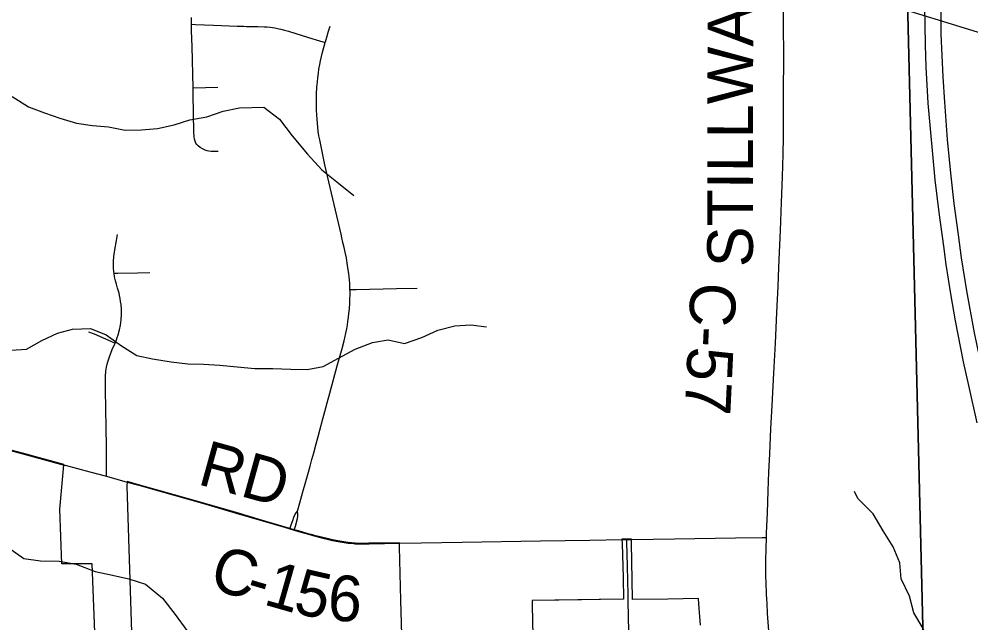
# Model space of a CAD drawing. Extents: x -6.4 to 34, y -4.2 to 22.
# Drawn here: x 5.93 to 7.115, y 16.08 to 16.831 of the extents above; entities that cross this region are included whole.
import ezdxf

# ---------------------------------------------------------------- set-up
doc = ezdxf.new("R2010")
doc.units = 0
for name, color, linetype in [('GM_X_City_Street', 7, 'Continuous'), ('GM_X_Corporation', 7, 'Continuous'), ('GM_X_County_Road', 7, 'Continuous'), ('GM_X_County_Road_Text', 7, 'Continuous'), ('GM_X_Minor_River', 7, 'Continuous'), ('GM_X_State_Route', 7, 'Continuous'), ('GM_X_Township_Road', 7, 'Continuous'), ('SH_Text', 7, 'Continuous')]:
    doc.layers.add(name, color=color, linetype=linetype)

msp = doc.modelspace()

# ---------------------------------------------------------------- linework, layer by layer
at = {"layer": 'GM_X_City_Street'}
msp.add_lwpolyline([(6.6887, 16.07), (6.6883, 16.0873), (6.6878, 16.1073), (6.6877, 16.1153), (6.6869, 16.15), (6.6863, 16.1805), (6.6862, 16.1837)], dxfattribs=at)
at = {"layer": 'GM_X_Corporation'}
for points in [[(7.0203, 17.4801), (7.0556, 16.0421), (7.0636, 15.9014), (7.2702, 15.904), (7.2926, 15.9044), (8.6815, 15.9311), (8.9, 15.9356), (8.9, 20.7065)], [(5.7185, 15.8776), (6.5599, 15.8933), (6.7596, 15.897), (6.8667, 15.898), (7.0636, 15.9014), (7.0556, 16.0421), (7.0203, 17.4801)], [(6.0241, 16.0683), (6.0209, 16.1536), (5.9979, 16.1536), (5.983, 16.1536), (5.9805, 16.2214), (5.9852, 16.2717), (5.9857, 16.277), (5.9342, 16.2911), (5.8874, 16.3034)], [(6.41, 15.9369), (6.405, 16.1081), (6.4035, 16.1745), (6.4035, 16.1797), (6.3653, 16.179), (6.3609, 16.1789), (6.356, 16.1788), (6.3519, 16.1789), (6.348, 16.1791), (6.3436, 16.1795), (6.3394, 16.1799), (6.3341, 16.1807), (6.329, 16.1815), (6.3244, 16.1824), (6.3199, 16.1833), (6.3132, 16.1849), (6.3078, 16.1861), (6.303, 16.1874), (6.2987, 16.1885), (6.2952, 16.1894), (6.2898, 16.1908), (6.2775, 16.1944), (6.2722, 16.1959), (6.2668, 16.1975), (6.26, 16.1995), (6.2314, 16.208), (6.1999, 16.2173), (6.1581, 16.2293), (6.1037, 16.2448), (6.0786, 16.2518), (6.0643, 16.2559), (6.0641, 16.2503), (6.0698, 16.0683)], [(6.7779, 16.077), (6.7758, 16.1035), (6.7753, 16.1103), (6.7372, 16.1096), (6.6934, 16.1089), (6.6929, 16.1335), (6.692, 16.179), (6.6919, 16.1843), (6.686, 16.1842), (6.6802, 16.1841), (6.6806, 16.1788), (6.6815, 16.1361), (6.682, 16.1095), (6.6536, 16.1091), (6.6517, 16.1091), (6.6299, 16.1088), (6.6252, 16.1087), (6.6015, 16.1083), (6.5967, 16.1083), (6.5683, 16.1078), (6.5684, 16.1021), (6.5692, 16.0635)]]:
    msp.add_lwpolyline(points, dxfattribs=at)
at = {"layer": 'GM_X_County_Road'}
for points in [[(6.8601, 16.1863), (6.8602, 16.1918), (6.8612, 16.2171), (6.8622, 16.2442), (6.8631, 16.2674), (6.8641, 16.2903), (6.8656, 16.3213), (6.867, 16.3503), (6.869, 16.3908), (6.8711, 16.4282), (6.873, 16.4662), (6.8746, 16.4987), (6.8756, 16.5224), (6.8763, 16.5414), (6.8773, 16.5684), (6.8787, 16.6032), (6.8799, 16.635), (6.8807, 16.6631), (6.8812, 16.6844), (6.8813, 16.706), (6.8814, 16.7372), (6.8815, 16.7863), (6.8811, 16.8228), (6.8808, 16.8652)], [(5.7737, 16.3333), (5.7748, 16.333), (5.8511, 16.3126), (5.8876, 16.3028), (5.9344, 16.2905), (5.9862, 16.2763)], [(5.9862, 16.2763), (5.9871, 16.2761), (6.0178, 16.268), (6.0386, 16.2624), (6.0645, 16.2553)], [(6.0645, 16.2553), (6.0788, 16.2513), (6.1039, 16.2442), (6.1583, 16.2288), (6.2001, 16.2167), (6.2316, 16.2075), (6.2602, 16.1989), (6.267, 16.1969), (6.2724, 16.1954), (6.2777, 16.1939), (6.29, 16.1903), (6.2954, 16.1889), (6.2989, 16.188), (6.3032, 16.1868), (6.308, 16.1856), (6.3134, 16.1843), (6.3201, 16.1827), (6.3246, 16.1818), (6.3292, 16.1809), (6.3343, 16.1801), (6.3396, 16.1794), (6.3438, 16.179), (6.3482, 16.1785), (6.3521, 16.1784), (6.3562, 16.1782), (6.3611, 16.1783), (6.3655, 16.1784), (6.4037, 16.1791)], [(6.4037, 16.1791), (6.4301, 16.1795), (6.4813, 16.1803), (6.5789, 16.182), (6.6404, 16.183), (6.6804, 16.1836)], [(6.6804, 16.1836), (6.6862, 16.1837), (6.6926, 16.1837)], [(6.6926, 16.1837), (6.7456, 16.1845), (6.8213, 16.1858), (6.8547, 16.1862), (6.8601, 16.1863)], [(6.8691, 15.9507), (6.8687, 15.9618), (6.8684, 15.9792), (6.8667, 16.0136), (6.8642, 16.0529), (6.8634, 16.0641), (6.8626, 16.0757), (6.8615, 16.0918), (6.8607, 16.1041), (6.8604, 16.1098), (6.8602, 16.1153), (6.8599, 16.121), (6.8597, 16.1252), (6.8595, 16.1312), (6.8593, 16.1369), (6.8593, 16.1416), (6.8592, 16.1465), (6.8593, 16.1529), (6.8594, 16.1582), (6.8601, 16.1863)]]:
    msp.add_lwpolyline(points, dxfattribs=at)
at = {"layer": 'GM_X_Minor_River'}
for points in [[(5.9211, 16.7349), (5.9415, 16.7223), (5.9615, 16.7146), (5.9808, 16.708), (6.0012, 16.7019), (6.0212, 16.6991), (6.0413, 16.6971), (6.0621, 16.6932), (6.0822, 16.6935), (6.1022, 16.6953), (6.1227, 16.6998), (6.1424, 16.7061), (6.1637, 16.7098), (6.1838, 16.7166), (6.2042, 16.721), (6.2345, 16.7217), (6.2541, 16.7067), (6.2699, 16.6862), (6.2887, 16.6633), (6.3067, 16.6438), (6.3275, 16.627), (6.3467, 16.6117)], [(5.9199, 16.4193), (5.9392, 16.4207), (5.9582, 16.4313), (5.9776, 16.4407), (5.9965, 16.4455), (6.0189, 16.4462), (6.0381, 16.4385), (6.0574, 16.4247), (6.0766, 16.4128), (6.0959, 16.4086), (6.1193, 16.4047), (6.1398, 16.4023), (6.1594, 16.4018), (6.1799, 16.4006), (6.2014, 16.3986), (6.2234, 16.3966), (6.2457, 16.3965), (6.2681, 16.3956), (6.2885, 16.3955), (6.3082, 16.3992), (6.3276, 16.4094), (6.3481, 16.4207), (6.3697, 16.4289), (6.3891, 16.4323), (6.4095, 16.4276), (6.4311, 16.4351), (6.4509, 16.4441), (6.4721, 16.4497), (6.4922, 16.4508), (6.5115, 16.4484)], [(7.1193, 15.8737), (7.0998, 15.8912), (7.0832, 15.911), (7.0765, 15.9308), (7.0744, 15.951), (7.0756, 15.9711), (7.0697, 15.9912), (7.0679, 16.0114), (7.062, 16.0311), (7.0614, 16.0528), (7.0551, 16.073), (7.0435, 16.0924), (7.0379, 16.1133), (7.0278, 16.135), (7.0261, 16.1547), (7.0175, 16.1745), (7.0051, 16.1947), (6.9927, 16.2157), (6.9739, 16.2347), (6.9694, 16.2435)], [(5.9161, 16.1743), (5.9357, 16.1602), (5.9565, 16.1574), (5.9796, 16.1566), (6.0011, 16.153), (6.0245, 16.1438), (6.0461, 16.1395), (6.0665, 16.1349), (6.0873, 16.1283), (6.1084, 16.1108), (6.1242, 16.0906), (6.1388, 16.0707)]]:
    msp.add_lwpolyline(points, dxfattribs=at)
at = {"layer": 'GM_X_State_Route'}
for points in [[(7.2156, 16.091), (7.2133, 16.0975), (7.206, 16.117), (7.188, 16.1712), (7.168, 16.2365), (7.1566, 16.2779), (7.137, 16.356), (7.1276, 16.3999), (7.1189, 16.4411), (7.1092, 16.4931), (7.1027, 16.5343), (7.0988, 16.5627), (7.0937, 16.6018), (7.0894, 16.6395), (7.0855, 16.6813), (7.0818, 16.7279), (7.08, 16.7594), (7.0776, 16.8125), (7.0772, 16.8681)], [(7.1223, 16.3289), (7.1117, 16.3752), (7.1054, 16.4049), (7.0953, 16.4558), (7.0896, 16.4895), (7.0837, 16.5258), (7.0806, 16.5487), (7.0749, 16.5907), (7.0699, 16.6313), (7.0611, 16.7268), (7.0588, 16.7718), (7.058, 16.7993), (7.0571, 16.8478)]]:
    msp.add_lwpolyline(points, dxfattribs=at)
at = {"layer": 'GM_X_Township_Road'}
msp.add_line((6.1464, 16.7456), (6.1771, 16.7465), dxfattribs=at)
for points in [[(6.8601, 16.1863), (6.8602, 16.1918), (6.8612, 16.2171), (6.8622, 16.2442), (6.8631, 16.2674), (6.8641, 16.2903), (6.8656, 16.3213), (6.867, 16.3503), (6.869, 16.3908), (6.8711, 16.4282), (6.873, 16.4662), (6.8746, 16.4987), (6.8756, 16.5224), (6.8763, 16.5414), (6.8773, 16.5684), (6.8787, 16.6032), (6.8799, 16.635), (6.8807, 16.6631), (6.8812, 16.6844), (6.8813, 16.706), (6.8814, 16.7372), (6.8815, 16.7863), (6.8811, 16.8228), (6.8808, 16.8652)], [(6.1776, 16.6664), (6.1715, 16.6665), (6.169, 16.6665), (6.166, 16.6668), (6.1638, 16.6673), (6.1616, 16.6681), (6.158, 16.6699), (6.1551, 16.6717), (6.1528, 16.6735), (6.1512, 16.6752), (6.1499, 16.6771), (6.1489, 16.6793), (6.1481, 16.6821), (6.1476, 16.6851), (6.1473, 16.6906), (6.1466, 16.7378), (6.1464, 16.7456), (6.1451, 16.7974), (6.1444, 16.8168), (6.1443, 16.8248), (6.1443, 16.8334)], [(6.1443, 16.8248), (6.1495, 16.8246), (6.1719, 16.8239), (6.2014, 16.8226), (6.206, 16.8225), (6.2097, 16.8224), (6.2131, 16.8223), (6.2141, 16.8223), (6.22, 16.8221), (6.2271, 16.822), (6.2352, 16.8218), (6.2388, 16.8216), (6.2425, 16.8213), (6.248, 16.8206), (6.2513, 16.8198), (6.2558, 16.8188), (6.2603, 16.8176), (6.2653, 16.8162), (6.2902, 16.8084), (6.3039, 16.8043), (6.311, 16.8022)], [(6.2724, 16.1954), (6.2738, 16.2004), (6.2763, 16.2097), (6.2766, 16.2127), (6.2766, 16.2159), (6.2763, 16.2191), (6.2793, 16.2293), (6.2832, 16.2431), (6.2868, 16.2558), (6.2893, 16.2646), (6.2921, 16.2751), (6.2942, 16.2831), (6.2966, 16.2918), (6.2996, 16.3029), (6.3021, 16.3119), (6.3042, 16.32), (6.308, 16.3339), (6.3117, 16.3476), (6.3134, 16.3538), (6.3167, 16.366), (6.3259, 16.4), (6.332, 16.4214), (6.3345, 16.4311), (6.3354, 16.4346), (6.3366, 16.4406), (6.3378, 16.4461), (6.3385, 16.4508), (6.3392, 16.4551), (6.3399, 16.4605), (6.3404, 16.4649), (6.3409, 16.4709), (6.3414, 16.4779), (6.3416, 16.4831), (6.3418, 16.4884), (6.3418, 16.4929), (6.3417, 16.4947), (6.3417, 16.497), (6.3414, 16.5018), (6.3412, 16.5069), (6.3408, 16.5104), (6.3403, 16.5148), (6.3396, 16.5194), (6.3382, 16.5278), (6.3372, 16.5344), (6.3358, 16.5413), (6.3345, 16.5471), (6.333, 16.5534), (6.3317, 16.5592), (6.3306, 16.5639), (6.3236, 16.5937), (6.3106, 16.65), (6.3041, 16.6809), (6.3031, 16.6862), (6.3022, 16.6913), (6.3016, 16.6968), (6.3011, 16.7012), (6.3007, 16.707), (6.3003, 16.7118), (6.3002, 16.7183), (6.3, 16.7236), (6.3, 16.7298), (6.3, 16.7309), (6.3001, 16.7379), (6.3005, 16.7466), (6.3011, 16.7531), (6.3016, 16.7584), (6.3024, 16.7639), (6.3031, 16.7689), (6.3041, 16.7747), (6.3049, 16.7794), (6.3061, 16.7847), (6.307, 16.7885), (6.3083, 16.7932), (6.3091, 16.7961), (6.311, 16.8022), (6.3113, 16.8031), (6.313, 16.8087), (6.3151, 16.8161), (6.317, 16.8226)], [(6.0386, 16.2624), (6.0387, 16.2701), (6.0388, 16.2837), (6.0387, 16.2993), (6.0374, 16.3701), (6.0374, 16.3869), (6.0378, 16.3932), (6.0385, 16.3982), (6.0399, 16.4037), (6.0411, 16.4074), (6.0423, 16.4109), (6.0441, 16.4155), (6.0459, 16.4202), (6.0493, 16.428), (6.051, 16.4322), (6.052, 16.435), (6.0533, 16.4385), (6.055, 16.4445), (6.0562, 16.4505), (6.057, 16.4572), (6.0575, 16.464), (6.0574, 16.4701), (6.0569, 16.4762), (6.0563, 16.4801), (6.0558, 16.4835), (6.055, 16.4872), (6.0543, 16.4902), (6.0524, 16.4965), (6.051, 16.5016), (6.0498, 16.5057), (6.0487, 16.5106), (6.0481, 16.515), (6.048, 16.5162), (6.0475, 16.5225), (6.0476, 16.5294), (6.048, 16.5363), (6.0486, 16.5408), (6.049, 16.5443), (6.0511, 16.556), (6.0525, 16.5633)], [(6.0481, 16.515), (6.0526, 16.5151), (6.0773, 16.5157), (6.0928, 16.5161)], [(6.3417, 16.4947), (6.3492, 16.4948), (6.3997, 16.4959), (6.4252, 16.4967)], [(6.0162, 16.4422), (6.0232, 16.4397), (6.0374, 16.4336), (6.0441, 16.4305), (6.0493, 16.428)], [(6.267, 16.1969), (6.2686, 16.2019), (6.2705, 16.2076), (6.2719, 16.2117), (6.2732, 16.2145), (6.2747, 16.2169), (6.2763, 16.2191)], [(6.8691, 15.9507), (6.8687, 15.9618), (6.8684, 15.9792), (6.8667, 16.0136), (6.8642, 16.0529), (6.8634, 16.0641), (6.8626, 16.0757), (6.8615, 16.0918), (6.8607, 16.1041), (6.8604, 16.1098), (6.8602, 16.1153), (6.8599, 16.121), (6.8597, 16.1252), (6.8595, 16.1312), (6.8593, 16.1369), (6.8593, 16.1416), (6.8592, 16.1465), (6.8593, 16.1529), (6.8594, 16.1582), (6.8601, 16.1863)]]:
    msp.add_lwpolyline(points, dxfattribs=at)
at = {"layer": 'SH_Text'}
msp.add_lwpolyline([(9.3252, 16.3385), (9.3252, 16.1385), (5.5217, 17.3069)], close=True, dxfattribs=at)

# ---------------------------------------------------------------- texts
at = {"layer": 'GM_X_County_Road_Text'}
for s, height, rotation, p in [('STILLWAGON RD', 0.056818, 89.9182, (6.8431, 16.5226)), ('C-57', 0.05682, 267.2726, (6.766, 16.5045)), ('RD', 0.05682, 344.5285, (6.1505, 16.253)), ('C', 0.0568, 343.3976, (6.1647, 16.1235)), ('1', 0.0568, 344.114, (6.2325, 16.1034)), ('5', 0.0568, 347.1364, (6.2694, 16.093)), ('6', 0.0568, 355.6971, (6.3126, 16.0838)), ('-', 0.0568, 343.5427, (6.2095, 16.1101))]:
    msp.add_text(s, height=height, rotation=rotation, dxfattribs=at).set_placement(p)

doc.saveas('drawing.dxf')
